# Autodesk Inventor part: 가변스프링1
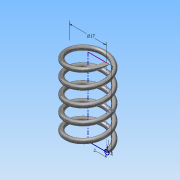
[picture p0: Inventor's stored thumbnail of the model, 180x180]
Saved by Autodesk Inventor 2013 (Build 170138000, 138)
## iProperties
Created: 2016-02
Part Number: 가변스프링1
Material: 스테인리스강
Document SubType Name: Modeling
Designer: Administrator
Mass: 6.69836 g
Surface Area: 16.8029 cm^2
Volume: 0.829005 cm^3
Density: 8.08 g/cm^3
Author: Administrator
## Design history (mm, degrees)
sketch "스케치1"
  geometry: L1 (0, 0)-(8.5, 0); L2 (8.5, 0)-(8.5, 35); L3 (8.5, 35)-(0, 35); L4 (0, 35)-(0, 0); C1 r 1 at (8.5, 0)
  constraints: 8 end point, 2 parallel, 1 centre point, 1 coincident, 1 horizontal, 1 perpendicular
  dimensions: "d0" = 35 distance of L1.end L2.end (derived); "d2" = 17 diameter of L2 L4; "d3" = 2 diameter of C1
feature "코일1" sketch "스케치1" pitch "d4" = 10; turns "d6" = 5; dims "d5" = 35 (= d0), "d7" = 0, angle "d8" = 90 deg, angle "d9" = 90 deg, "d10" = 0, "d11" = 0
feature "분할1"
node "작업 평면1"
feature "분할2"
node "솔리드1"
other parameters: "d12" = 90 deg
